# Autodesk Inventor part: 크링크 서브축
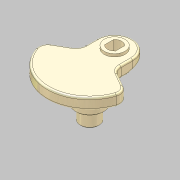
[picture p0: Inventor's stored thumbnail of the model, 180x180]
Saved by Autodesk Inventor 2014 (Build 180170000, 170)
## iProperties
Manager: KYOUNG IL JANG
Company: 한국ATC센터
Created: 2012-10
Part Number: 크링크 서브축
Document SubType Name: Modeling
Density: 1 g/cm^3
Checked By: KYOUNG IL JANG
Vendor: CBT Solutions
Designer: KYOUNG IL JANG
Material: Generic
Appearance: _시험_금속-티타늄(광택)
Author: KYOUNG IL JANG
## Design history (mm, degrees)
sketch "스케치1"
  geometry: L1 (-19, 109.368)-(-19, 91.368); L2 (-19, 91.368)-(-44.545, 76.619); L3 (19, 109.368)-(19, 91.368); L4 (19, 91.368)-(44.545, 76.619); C1 r 32.5 at (0, 83) reference; C2 r 10 at (0, 83); C3 r 17.5 at (0, 83); A1 r 45 centre (0, 83) between (-44.545, 76.619) and (44.545, 76.619); A2 r 32.5 centre (0, 83) between (-19, 109.368) and (19, 109.368); A3 r 19 centre (0, 109.368) between (19, 109.368) and (-19, 109.368); 1 further point
  constraints: 8 end point, 6 point on circle, 5 centre point, 4 coincident, 2 equal length, 1 horizontal alignment, 1 parallel, 1 tangent, 1 vertical, 1 vertical alignment
  dimensions: "d0" = 20 diameter of C2; "d1" = 35 diameter of C3; "d2" = 90 diameter of A1 (derived); "d3" = 65 diameter of A2 (derived); "d4" = 120 deg angle of L3 L4; "d5" = 19 radius of A3 (derived); "d6" = 18 distance of L1.start L1.end (derived)
extrude "돌출1" new body sketch "스케치1" distance "d7" = 12; taper "d8" = 0 deg
extrude "돌출2" join sketch "스케치1" distance "d9" = 5; taper "d10" = 0 deg
extrude "돌출3" join sketch "스케치1" distance "d11" = 41; taper "d12" = 0 deg
sketch "스케치2"
  geometry: C1 r 7.5 at (0, 109.368); C2 r 11 at (0, 109.368); A1 r 19 centre (0, 109.368) between (19, 109.368) and (-19, 109.368) reference; 1 further point
  constraints: 2 centre point, 2 coincident
  dimensions: "d13" = 15 diameter of C1; "d14" = 22 diameter of C2
extrude "돌출4" join sketch "스케치2" distance "d15" = 3; taper "d16" = 0 deg
extrude "돌출6" cut sketch "스케치2" stored distance "d19" = 10; taper "d20" = 0 deg
sketch "스케치3"
  geometry: L1 (-5.75, 4.815)-(-5.75, -4.815); L2 (5.75, 4.815)-(5.75, -4.815); A1 r 7.5 centre (0, 0) between (-5.75, 4.815) and (-5.75, -4.815) reference; 1 further point
  constraints: 4 end point, 4 point on circle, 2 parallel, 1 vertical
  dimensions: "d21" = 11.5 distance between parallel lines of L2 L1
extrude "돌출7" join sketch "스케치3" stored distance "d22" = 10; taper "d23" = 0 deg
sketch "스케치4"
  geometry: C1 r 10 at (0, 0) reference; C2 r 15 at (0, 0); 1 further point
  constraints: 1 centre point, 1 coincident
  dimensions: "d30" = 30 diameter of C2
extrude "돌출8" join sketch "스케치4" distance "d28" = 21; taper "d29" = 0 deg
chamfer "모따기1" distance "d31" = 1; stored, may be unused: second distance "d32" = 2, angle "d33" = 45 deg
sketch "스케치5"
  geometry: L1 (-19, 91.368)-(-19, 109.368) reference; L2 (19, 109.368)-(19, 91.368) reference; C1 r 9 at (0, 83); 3 further points
  constraints: 2 point on line, 1 centre point, 1 horizontal alignment
  dimensions: "d34" = 21 vertical distance of point (-19, 104) C1.centre (derived)
node "작업 평면1"
  node "작업축2"
sketch "스케치6"
  geometry: L1 (0, 50)-(38, 50); L2 (38, 50)-(38, 0); L3 (38, 0)-(0, 0); L4 (0, 0)-(0, 50); L5 (0, -12.202)-(0, 5.185) reference; L6 (38, 5.185)-(38, -12.202) reference; 2 further points
  constraints: 8 end point, 2 collinear, 1 point on line
  dimensions: "d37" = 50 distance from line of L1 L3.end
extrude "돌출9" cut sketch "스케치6" stored distance "d38" = 20.7; taper "d39" = 0 deg
fillet "모깎기1" dims "d26" = 10, "d27" = 2
node "솔리드1"
node "참조1"
other parameters: "d35" = -15 deg (derived)
